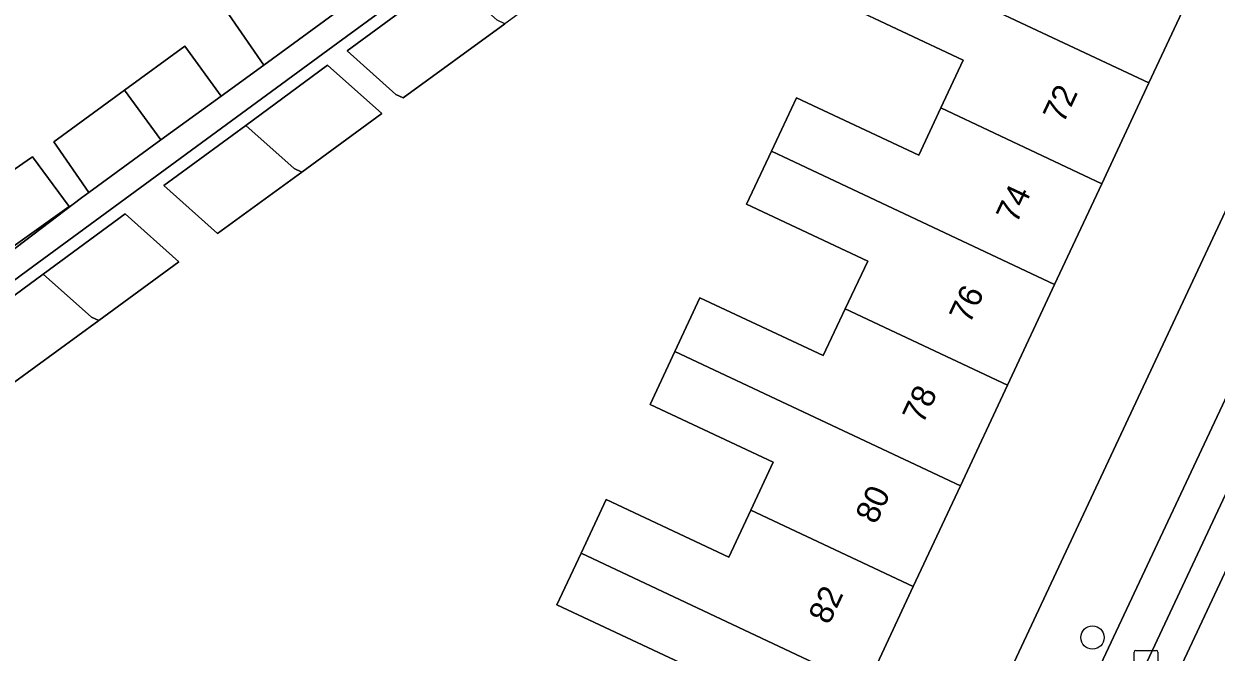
# Model space of a CAD drawing. Extents: x 159817 to 160765, y 380688 to 381638.
# Drawn here: x 160042.8 to 160093.1, y 381284.2 to 381310.6 of the extents above; entities that cross this region are included whole.
import ezdxf

# ---------------------------------------------------------------- set-up
doc = ezdxf.new("R2010")
doc.units = 0
for name, color, linetype in [('IMGEO_Boom', 7, 'Continuous'), ('IMGEO_Erf', 7, 'Continuous'), ('IMGEO_Kolk', 7, 'Continuous'), ('IMGEO_Pand', 7, 'Continuous'), ('IMGEO_Pand_nummerreeks', 7, 'Continuous'), ('IMGEO_Parkeervlak_open', 7, 'Continuous'), ('IMGEO_Rijbaan_lokaal_gesloten', 7, 'Continuous'), ('IMGEO_Voetpad_open', 7, 'Continuous')]:
    doc.layers.add(name, color=color, linetype=linetype)

msp = doc.modelspace()

# ---------------------------------------------------------------- linework, layer by layer
at = {"layer": 'IMGEO_Boom'}
msp.add_circle((160087.849, 381284.781), 0.489, dxfattribs=at)
at = {"layer": 'IMGEO_Erf'}
for points in [[(160092.258, 381312.476), (160090.221, 381308.123), (160088.236, 381303.883), (160086.251, 381299.642), (160084.266, 381295.402), (160082.281, 381291.162), (160080.296, 381286.922), (160078.311, 381282.681), (160076.326, 381278.441), (160074.34, 381274.2), (160072.355, 381269.959), (160070.371, 381265.72), (160068.515, 381261.756), (160069.074, 381261.494), (160066.985, 381257.032), (160065.066, 381252.933), (160065.564, 381252.7), (160064.302, 381250), (160063.49, 381248.262), (160061.17, 381243.297), (160064.796, 381241.634), (160068.719, 381250), (160100.669, 381318.138)], [(160060.315, 381312.948), (160056.049, 381309.817), (160051.783, 381306.687), (160047.516, 381303.556), (160043.25, 381300.426), (160038.984, 381297.296)], [(160070.462, 381283.731), (160065.286, 381286.154), (160066.305, 381288.331), (160067.36, 381290.586), (160072.522, 381288.17), (160073.447, 381290.146), (160074.393, 381292.167), (160069.21, 381294.593), (160070.253, 381296.822), (160071.311, 381299.081), (160076.505, 381296.65), (160077.432, 381298.618), (160078.379, 381300.627), (160073.276, 381303.018), (160074.324, 381305.255), (160075.377, 381307.504), (160080.534, 381305.089), (160081.462, 381307.071), (160082.405, 381309.085), (160077.257, 381311.496)], [(160029.83, 381291.581), (160045.257, 381303.288), (160045.558, 381303.508), (160044.089, 381305.65), (160047.066, 381307.821), (160049.604, 381309.671), (160051.134, 381307.573), (160052.931, 381308.869), (160051.462, 381311.011)]]:
    msp.add_lwpolyline(points, dxfattribs=at)
for points in [[(160063.09, 381310.612), (160058.811, 381307.491), (160058.49, 381307.641), (160056.439, 381309.469), (160060.705, 381312.6), (160064.15, 381315.13), (160066.46, 381313.071)], [(160050.984, 381301.782), (160048.719, 381303.802), (160052.174, 381306.338), (160055.623, 381308.87), (160057.909, 381306.833), (160054.532, 381304.37)], [(160041.149, 381303.609), (160042.957, 381304.863), (160043.183, 381305.02), (160044.736, 381302.929), (160040.89, 381300.182), (160037.537, 381297.855), (160036.016, 381300.046), (160039.317, 381302.338)], [(160049.359, 381300.597), (160045.975, 381298.128), (160042.438, 381295.548), (160040.196, 381297.547), (160043.642, 381300.076), (160047.098, 381302.613)]]:
    msp.add_lwpolyline(points, close=True, dxfattribs=at)
at = {"layer": 'IMGEO_Kolk'}
for p, q in [((160089.603, 381283.314), (160089.603, 381284.166)), ((160089.678, 381284.24), (160090.53, 381284.24)), ((160090.604, 381284.166), (160090.604, 381283.314))]:
    msp.add_line(p, q, dxfattribs=at)
for points in [[(160089.603, 381283.314), (160089.603, 381284.166)], [(160089.678, 381284.24), (160090.53, 381284.24)], [(160090.604, 381284.166), (160090.604, 381283.314)]]:
    msp.add_lwpolyline(points, dxfattribs=at)
for centre, start, end in [((160089.68, 381284.164), 91.552, 178.448), ((160089.68, 381284.164), 91.552, 178.448), ((160090.528, 381284.164), 1.552, 88.448), ((160090.528, 381284.164), 1.552, 88.448)]:
    msp.add_arc(centre, 0.0765, start, end, dxfattribs=at)
at = {"layer": 'IMGEO_Pand'}
for points in [[(160086.121, 381315.373), (160085.483, 381315.674), (160084.483, 381313.538), (160079.34, 381315.946), (160078.304, 381313.732), (160090.221, 381308.123), (160092.258, 381312.476)], [(160081.462, 381307.071), (160088.236, 381303.883), (160090.221, 381308.123), (160078.304, 381313.732), (160077.257, 381311.496), (160082.405, 381309.085)], [(160056.218, 381311.266), (160054.69, 381313.365), (160051.462, 381311.011), (160052.931, 381308.869)], [(160063.09, 381310.612), (160062.765, 381310.764), (160060.705, 381312.6), (160056.439, 381309.469), (160058.49, 381307.641), (160058.811, 381307.491)], [(160048.597, 381305.723), (160051.134, 381307.573), (160049.604, 381309.671), (160047.066, 381307.821)], [(160057.909, 381306.833), (160055.623, 381308.87), (160052.174, 381306.338), (160054.215, 381304.518), (160054.532, 381304.37)], [(160048.597, 381305.723), (160047.066, 381307.821), (160044.089, 381305.65), (160045.558, 381303.508)], [(160081.462, 381307.071), (160080.534, 381305.089), (160075.377, 381307.504), (160074.324, 381305.255), (160086.251, 381299.642), (160088.236, 381303.883)], [(160054.532, 381304.37), (160054.215, 381304.518), (160052.174, 381306.338), (160048.719, 381303.802), (160050.984, 381301.782)], [(160041.149, 381303.609), (160039.317, 381302.338), (160040.89, 381300.182), (160044.736, 381302.929), (160043.183, 381305.02), (160042.957, 381304.863)], [(160074.324, 381305.255), (160073.276, 381303.018), (160078.379, 381300.627), (160077.432, 381298.618), (160084.266, 381295.402), (160086.251, 381299.642)], [(160049.359, 381300.597), (160047.098, 381302.613), (160043.642, 381300.076), (160045.666, 381298.272), (160045.975, 381298.128)], [(160045.975, 381298.128), (160045.666, 381298.272), (160043.642, 381300.076), (160040.196, 381297.547), (160042.438, 381295.548)], [(160082.281, 381291.162), (160084.266, 381295.402), (160077.432, 381298.618), (160076.505, 381296.65), (160071.311, 381299.081), (160070.253, 381296.822)], [(160080.296, 381286.922), (160082.281, 381291.162), (160070.253, 381296.822), (160069.21, 381294.593), (160074.393, 381292.167), (160073.447, 381290.146)], [(160078.311, 381282.681), (160080.296, 381286.922), (160073.447, 381290.146), (160072.522, 381288.17), (160067.36, 381290.586), (160066.305, 381288.331)], [(160078.311, 381282.681), (160066.305, 381288.331), (160065.286, 381286.154), (160070.462, 381283.731), (160069.491, 381281.657), (160076.326, 381278.441)]]:
    msp.add_lwpolyline(points, close=True, dxfattribs=at)
at = {"layer": 'IMGEO_Parkeervlak_open'}
for points in [[(160070.611, 381242.154), (160074.295, 381250), (160101.43, 381307.786)], [(160100.275, 381306.758), (160099.052, 381306.314), (160098.772, 381306.149), (160072.368, 381250), (160070.305, 381245.613)]]:
    msp.add_lwpolyline(points, dxfattribs=at)
at = {"layer": 'IMGEO_Rijbaan_lokaal_gesloten'}
for points in [[(160094.482, 381289.744), (160102.66, 381307.196), (160101.43, 381307.786), (160074.295, 381250), (160070.611, 381242.154), (160071.864, 381241.581), (160074.041, 381246.213)], [(160075.165, 381240.07), (160086.808, 381264.863), (160102.688, 381298.872), (160105.882, 381305.652), (160102.66, 381307.196), (160094.482, 381289.744), (160074.041, 381246.213), (160071.864, 381241.581)]]:
    msp.add_lwpolyline(points, close=True, dxfattribs=at)
at = {"layer": 'IMGEO_Voetpad_open'}
for points in [[(160101.43, 381307.786), (160102.145, 381309.306), (160100.344, 381310.181), (160107.377, 381325.246), (160109.242, 381324.385), (160109.962, 381325.916), (160105.356, 381328.134), (160101.76, 381320.464), (160100.669, 381318.138), (160068.719, 381250), (160064.796, 381241.634), (160062.588, 381238.706)], [(160038.984, 381297.296), (160043.25, 381300.426), (160047.516, 381303.556), (160051.783, 381306.687), (160056.049, 381309.817), (160060.315, 381312.948)], [(160056.218, 381311.266), (160052.931, 381308.869), (160051.134, 381307.573), (160048.597, 381305.723), (160045.558, 381303.508), (160045.257, 381303.288), (160029.83, 381291.581)], [(160070.305, 381245.613), (160072.368, 381250), (160098.772, 381306.149), (160099.052, 381306.314), (160100.275, 381306.758)]]:
    msp.add_lwpolyline(points, dxfattribs=at)

# ---------------------------------------------------------------- texts
at = {"layer": 'IMGEO_Pand_nummerreeks'}
for s, p in [('72', (160086.623, 381306.382)), ('74', (160084.649, 381302.165)), ('76', (160082.674, 381297.945)), ('78', (160080.699, 381293.728)), ('80', (160078.724, 381289.508)), ('82', (160076.746, 381285.283))]:
    msp.add_text(s, height=1, rotation=64.9145, dxfattribs=at).set_placement(p)

doc.saveas('drawing.dxf')
